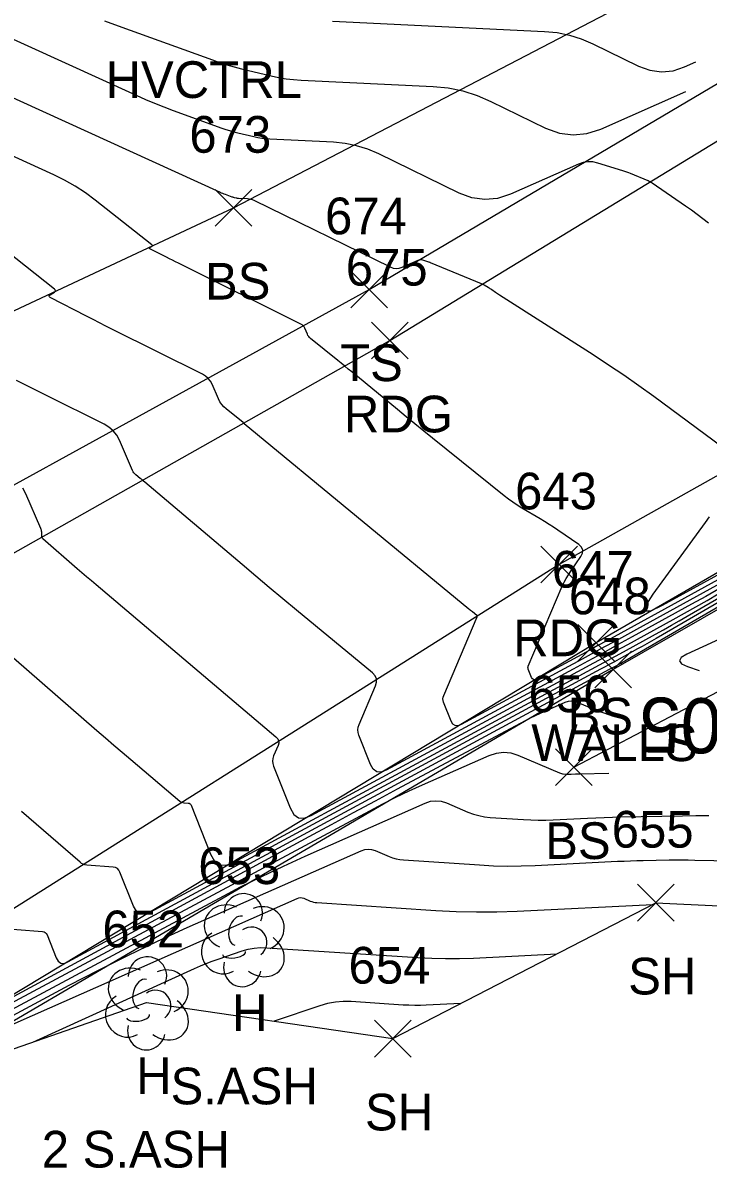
# Model space of a CAD drawing. Extents: x 1650836 to 1652450, y 332578 to 333908.
# Drawn here: x 1652071.1 to 1652108.4, y 332626 to 332688.4 of the extents above; entities that cross this region are included whole.
import ezdxf

# ---------------------------------------------------------------- set-up
doc = ezdxf.new("R2010")
doc.units = 0
for name, color, linetype in [('C_A', 7, 'Continuous'), ('L_A', 7, 'Continuous'), ('L_C', 7, 'Continuous'), ('L_I', 7, 'Continuous'), ('L_TIC', 7, 'Continuous'), ('LELB', 7, 'Continuous'), ('LSOGCMA', 7, 'Continuous'), ('LSOGCMA_T', 7, 'Continuous'), ('LSOGCMI', 7, 'Continuous'), ('LSOGP', 7, 'Continuous'), ('LTD', 7, 'Continuous'), ('LWS', 7, 'Continuous'), ('P_A', 7, 'Continuous'), ('P_I', 7, 'Continuous'), ('P_TIC', 7, 'Continuous'), ('PEU', 7, 'Continuous')]:
    doc.layers.add(name, color=color, linetype=linetype)

msp = doc.modelspace()

# ---------------------------------------------------------------- linework, layer by layer
at = {"layer": 'L_TIC'}
for points in [[(1652081.555, 332677.298), (1652083.555, 332679.298)], [(1652083.555, 332677.298), (1652081.555, 332679.298)], [(1652088.949, 332672.854), (1652090.949, 332674.854)], [(1652090.949, 332672.854), (1652088.949, 332674.854)], [(1652101.311, 332653.602), (1652103.311, 332655.602)], [(1652103.311, 332653.602), (1652101.311, 332655.602)], [(1652102.236, 332652.15), (1652104.236, 332654.15)], [(1652104.236, 332652.15), (1652102.236, 332654.15)], [(1652100.093, 332646.816), (1652102.093, 332648.816)], [(1652102.093, 332646.816), (1652100.093, 332648.816)], [(1652104.571, 332639.437), (1652106.571, 332641.437)], [(1652106.571, 332639.437), (1652104.571, 332641.437)], [(1652090.228, 332632.028), (1652092.228, 332634.028)], [(1652092.228, 332632.028), (1652090.228, 332634.028)]]:
    msp.add_lwpolyline(points, dxfattribs=at)
at = {"layer": 'LELB'}
for points in [[(1652048.756, 332662.461), (1652082.555, 332678.298), (1652130.366, 332703.201), (1652148.083, 332715.406), (1652159.47, 332726.367), (1652148.02, 332734.227), (1652128.413, 332739.339), (1652116.951, 332747.33), (1652106.793, 332756.875), (1652094.604, 332761.138), (1652083.802, 332764.466), (1652074.482, 332770.284), (1652065.17, 332770.428), (1652062.989, 332774.387), (1652054.537, 332784.724), (1652034.993, 332796.475), (1652025.062, 332801.1), (1652009.772, 332808.074), (1651988.967, 332816.401), (1651980.006, 332832.954), (1651960.575, 332843.477), (1651932.852, 332862.75), (1651890.753, 332886.019), (1651847.527, 332911.35)], [(1652054.928, 332654.589), (1652089.949, 332673.854), (1652132.975, 332699.313), (1652151.656, 332710.875), (1652169.833, 332727.743)], [(1652101.093, 332647.816), (1652114.189, 332654.693), (1652146.823, 332664.15), (1652153.664, 332667.075), (1652184.838, 332674.254)], [(1652114.452, 332661.6), (1652102.311, 332654.602), (1652064.084, 332631.537)]]:
    msp.add_lwpolyline(points, dxfattribs=at)
at = {"layer": 'LSOGCMA'}
for points in [[(1652075.521, 332688.493), (1652076.47, 332688.139), (1652081.4, 332686.353), (1652081.792, 332686.217), (1652082.188, 332686.092), (1652082.587, 332685.979), (1652082.989, 332685.876), (1652084.605, 332685.49), (1652085.011, 332685.402), (1652085.419, 332685.334), (1652085.83, 332685.286), (1652086.243, 332685.256), (1652093.433, 332684.907), (1652094.251, 332684.826), (1652095.048, 332684.665), (1652095.824, 332684.422), (1652096.58, 332684.099), (1652099.561, 332682.643), (1652100.308, 332682.367), (1652101.058, 332682.265), (1652101.812, 332682.338), (1652102.568, 332682.586), (1652107.206, 332684.634)], [(1652103.058, 332650.647), (1652102.687, 332650.778), (1652102.51, 332650.841), (1652102.335, 332650.908), (1652102.161, 332650.977), (1652101.988, 332651.048), (1652101.298, 332651.341), (1652101.125, 332651.396), (1652100.953, 332651.413), (1652100.781, 332651.393), (1652100.61, 332651.336), (1652099.268, 332650.743), (1652098.988, 332650.616), (1652098.711, 332650.484), (1652098.437, 332650.347), (1652098.165, 332650.204), (1652091.477, 332646.62), (1652090.272, 332645.974), (1652089.068, 332645.327), (1652087.865, 332644.678), (1652086.662, 332644.029), (1652069.011, 332634.495)]]:
    msp.add_lwpolyline(points, dxfattribs=at)
at = {"layer": 'LSOGCMI'}
for points in [[(1652108.436, 332677.463), (1652108.129, 332677.701), (1652107.819, 332677.935), (1652107.504, 332678.163), (1652107.186, 332678.387), (1652105.369, 332679.642), (1652105.317, 332679.676), (1652105.264, 332679.707), (1652105.209, 332679.735), (1652105.152, 332679.76), (1652104.192, 332680.158), (1652104.088, 332680.199), (1652103.984, 332680.238), (1652103.879, 332680.275), (1652103.773, 332680.309), (1652102.396, 332680.739), (1652102.132, 332680.798), (1652101.871, 332680.808), (1652101.613, 332680.769), (1652101.358, 332680.681), (1652097.642, 332679.039), (1652096.939, 332678.809), (1652096.24, 332678.742), (1652095.544, 332678.836), (1652094.851, 332679.093), (1652090.462, 332681.236), (1652089.869, 332681.49), (1652089.26, 332681.68), (1652088.634, 332681.807), (1652087.992, 332681.87), (1652084.538, 332682.038), (1652084.315, 332682.054), (1652084.094, 332682.08), (1652083.875, 332682.117), (1652083.657, 332682.163), (1652082.788, 332682.371), (1652082.572, 332682.426), (1652082.358, 332682.487), (1652082.145, 332682.554), (1652081.934, 332682.627), (1652079.284, 332683.587), (1652078.775, 332683.778), (1652078.269, 332683.978), (1652077.768, 332684.189), (1652077.271, 332684.41), (1652061.577, 332691.567)], [(1652058.73, 332689.68), (1652081.818, 332679.151), (1652081.887, 332679.12), (1652081.957, 332679.091), (1652082.028, 332679.063), (1652082.099, 332679.036), (1652082.469, 332678.902), (1652082.498, 332678.892), (1652082.528, 332678.882), (1652082.558, 332678.874), (1652082.588, 332678.866), (1652082.709, 332678.837), (1652082.74, 332678.831), (1652082.77, 332678.826), (1652082.801, 332678.822), (1652082.832, 332678.82), (1652083.314, 332678.796), (1652083.404, 332678.788), (1652083.491, 332678.77), (1652083.576, 332678.743), (1652083.659, 332678.708), (1652091.094, 332675.077), (1652091.255, 332675.017), (1652091.418, 332674.995), (1652091.581, 332675.011), (1652091.745, 332675.065), (1652092.613, 332675.448), (1652092.673, 332675.468), (1652092.733, 332675.478), (1652092.794, 332675.475), (1652092.855, 332675.462), (1652093.177, 332675.361), (1652093.202, 332675.353), (1652093.226, 332675.345), (1652093.251, 332675.336), (1652093.275, 332675.326), (1652096.052, 332674.176), (1652096.092, 332674.159), (1652096.132, 332674.14), (1652096.17, 332674.12), (1652096.208, 332674.098), (1652096.429, 332673.968), (1652096.479, 332673.939), (1652096.527, 332673.908), (1652096.575, 332673.877), (1652096.623, 332673.845), (1652096.836, 332673.698), (1652096.888, 332673.663), (1652096.94, 332673.629), (1652096.992, 332673.595), (1652097.044, 332673.561), (1652102.154, 332670.297), (1652102.993, 332669.751), (1652103.822, 332669.192), (1652104.642, 332668.619), (1652105.452, 332668.032), (1652109.658, 332664.932)], [(1652087.949, 332688.474), (1652099.502, 332687.913), (1652100.186, 332687.846), (1652100.852, 332687.711), (1652101.501, 332687.508), (1652102.132, 332687.238), (1652104.623, 332686.021), (1652105.247, 332685.79), (1652105.874, 332685.705), (1652106.504, 332685.766), (1652107.136, 332685.973), (1652107.753, 332686.246)], [(1652110.967, 332659.136), (1652103.297, 332654.925), (1652102.855, 332654.683), (1652102.413, 332654.442), (1652101.97, 332654.201), (1652101.527, 332653.961), (1652099.037, 332652.617), (1652098.959, 332652.588), (1652098.892, 332652.593), (1652098.838, 332652.631), (1652098.796, 332652.704), (1652098.615, 332653.16), (1652098.603, 332653.202), (1652098.599, 332653.243), (1652098.604, 332653.285), (1652098.617, 332653.326), (1652100.468, 332657.677), (1652100.568, 332657.894), (1652100.678, 332658.105), (1652100.799, 332658.309), (1652100.931, 332658.508), (1652101.482, 332659.29), (1652101.578, 332659.478), (1652101.59, 332659.651), (1652101.518, 332659.809), (1652101.363, 332659.952), (1652100.232, 332660.728), (1652099.991, 332660.89), (1652099.748, 332661.047), (1652099.503, 332661.201), (1652099.254, 332661.35), (1652098.255, 332661.939), (1652098.008, 332662.091), (1652097.767, 332662.251), (1652097.532, 332662.42), (1652097.303, 332662.598), (1652093.399, 332665.744), (1652092.917, 332666.133), (1652092.437, 332666.524), (1652091.958, 332666.915), (1652091.48, 332667.309), (1652088.997, 332669.359), (1652088.807, 332669.515), (1652088.616, 332669.671), (1652088.425, 332669.827), (1652088.234, 332669.982), (1652086.749, 332671.182), (1652086.696, 332671.23), (1652086.65, 332671.283), (1652086.611, 332671.341), (1652086.579, 332671.404), (1652086.437, 332671.732), (1652086.398, 332671.804), (1652086.349, 332671.865), (1652086.29, 332671.917), (1652086.221, 332671.96), (1652079.546, 332675.278), (1652079.385, 332675.359), (1652079.224, 332675.44), (1652079.064, 332675.521), (1652078.904, 332675.603), (1652078, 332676.07), (1652077.979, 332676.084), (1652077.971, 332676.1), (1652077.977, 332676.116), (1652077.997, 332676.133), (1652078.103, 332676.202), (1652078.124, 332676.22), (1652078.131, 332676.238), (1652078.125, 332676.257), (1652078.107, 332676.276), (1652075.014, 332678.719), (1652074.48, 332679.115), (1652073.925, 332679.478), (1652073.349, 332679.806), (1652072.753, 332680.1), (1652055.884, 332687.793)], [(1652109.24, 332657.915), (1652104.512, 332655.319), (1652103.527, 332654.78), (1652102.541, 332654.242), (1652101.554, 332653.705), (1652100.566, 332653.17), (1652094.951, 332650.138), (1652094.774, 332650.072), (1652094.624, 332650.084), (1652094.503, 332650.171), (1652094.409, 332650.335), (1652094.002, 332651.36), (1652093.975, 332651.453), (1652093.966, 332651.546), (1652093.977, 332651.639), (1652094.007, 332651.732), (1652095.827, 332656.01), (1652095.833, 332656.031), (1652095.831, 332656.051), (1652095.823, 332656.069), (1652095.808, 332656.086), (1652095.566, 332656.28), (1652095.52, 332656.318), (1652095.474, 332656.355), (1652095.427, 332656.393), (1652095.381, 332656.431), (1652083.14, 332666.535), (1652083.123, 332666.55), (1652083.106, 332666.564), (1652083.088, 332666.578), (1652083.071, 332666.592), (1652082.146, 332667.339), (1652082.018, 332667.456), (1652081.907, 332667.585), (1652081.812, 332667.727), (1652081.733, 332667.882), (1652081.386, 332668.68), (1652081.292, 332668.855), (1652081.173, 332669.006), (1652081.028, 332669.133), (1652080.859, 332669.235), (1652075.954, 332671.674), (1652075.6, 332671.85), (1652075.248, 332672.028), (1652074.896, 332672.207), (1652074.545, 332672.388), (1652072.563, 332673.41), (1652072.517, 332673.442), (1652072.5, 332673.477), (1652072.513, 332673.512), (1652072.556, 332673.549), (1652072.79, 332673.701), (1652072.834, 332673.74), (1652072.85, 332673.779), (1652072.838, 332673.821), (1652072.797, 332673.863), (1652066.014, 332679.221)], [(1652109.08, 332657.566), (1652108.298, 332657.128), (1652107.514, 332656.694), (1652104.275, 332654.916), (1652103.473, 332654.477), (1652102.67, 332654.039), (1652101.867, 332653.602), (1652101.062, 332653.167), (1652090.865, 332647.659), (1652090.589, 332647.557), (1652090.357, 332647.575), (1652090.167, 332647.711), (1652090.021, 332647.966), (1652089.389, 332649.56), (1652089.347, 332649.705), (1652089.333, 332649.85), (1652089.35, 332649.994), (1652089.397, 332650.138), (1652090.295, 332652.251), (1652090.351, 332652.451), (1652090.341, 332652.635), (1652090.265, 332652.803), (1652090.124, 332652.955), (1652085.993, 332656.368), (1652085.248, 332656.986), (1652084.504, 332657.606), (1652083.763, 332658.229), (1652083.023, 332658.854), (1652077.713, 332663.355), (1652077.654, 332663.405), (1652077.594, 332663.455), (1652077.534, 332663.504), (1652077.473, 332663.553), (1652077.231, 332663.749), (1652077.174, 332663.801), (1652077.125, 332663.858), (1652077.083, 332663.921), (1652077.048, 332663.99), (1652076.335, 332665.629), (1652076.186, 332665.907), (1652075.996, 332666.146), (1652075.767, 332666.348), (1652075.497, 332666.511), (1652072.361, 332668.07), (1652071.816, 332668.342), (1652071.272, 332668.617), (1652070.728, 332668.893)], [(1652071.052, 332663.039), (1652071.218, 332662.73), (1652072.042, 332660.836), (1652072.059, 332660.79), (1652072.071, 332660.743), (1652072.079, 332660.694), (1652072.082, 332660.645), (1652072.083, 332660.447), (1652072.088, 332660.399), (1652072.102, 332660.356), (1652072.125, 332660.317), (1652072.158, 332660.282), (1652074.034, 332658.652), (1652074.29, 332658.43), (1652074.547, 332658.208), (1652074.805, 332657.988), (1652075.064, 332657.769), (1652084.865, 332649.478), (1652084.96, 332649.373), (1652085.01, 332649.259), (1652085.017, 332649.134), (1652084.979, 332648.998), (1652084.74, 332648.436), (1652084.694, 332648.295), (1652084.678, 332648.153), (1652084.691, 332648.012), (1652084.733, 332647.87), (1652085.634, 332645.596), (1652085.832, 332645.25), (1652086.089, 332645.066), (1652086.404, 332645.042), (1652086.779, 332645.18), (1652101.558, 332653.163), (1652102.179, 332653.499), (1652102.799, 332653.836), (1652103.419, 332654.174), (1652104.038, 332654.513), (1652106.513, 332655.872), (1652107.13, 332656.213), (1652107.746, 332656.558), (1652108.359, 332656.907), (1652108.971, 332657.26)], [(1652066.86, 332656.989), (1652075.112, 332649.816), (1652075.57, 332649.419), (1652076.029, 332649.024), (1652076.489, 332648.631), (1652076.951, 332648.239), (1652079.633, 332645.97), (1652079.681, 332645.936), (1652079.732, 332645.91), (1652079.787, 332645.892), (1652079.845, 332645.883), (1652080.085, 332645.865), (1652080.14, 332645.853), (1652080.186, 332645.83), (1652080.222, 332645.793), (1652080.249, 332645.743), (1652081.306, 332643.076), (1652081.521, 332642.701), (1652081.8, 332642.5), (1652082.143, 332642.474), (1652082.55, 332642.624), (1652102.055, 332653.159), (1652102.492, 332653.396), (1652102.929, 332653.633), (1652103.365, 332653.871), (1652103.801, 332654.11), (1652105.544, 332655.067), (1652105.979, 332655.307), (1652106.412, 332655.55), (1652106.844, 332655.796), (1652107.274, 332656.044), (1652115.608, 332660.886)], [(1652108.479, 332661.466), (1652108.253, 332661.149), (1652105.399, 332657.253), (1652105.018, 332656.65), (1652104.98, 332656.347), (1652105.285, 332656.346), (1652105.933, 332656.645), (1652112.693, 332660.356)], [(1652069.326, 332639.091), (1652072.141, 332638.871), (1652072.226, 332638.854), (1652072.296, 332638.817), (1652072.352, 332638.761), (1652072.393, 332638.685), (1652072.888, 332637.436), (1652072.998, 332637.244), (1652073.141, 332637.142), (1652073.316, 332637.128), (1652073.524, 332637.205), (1652103.047, 332653.152), (1652103.117, 332653.189), (1652103.187, 332653.227), (1652103.257, 332653.265), (1652103.326, 332653.304), (1652103.605, 332653.457), (1652103.675, 332653.495), (1652103.744, 332653.534), (1652103.813, 332653.573), (1652103.882, 332653.613), (1652116.085, 332660.703)], [(1652115.847, 332660.794), (1652105.578, 332654.829), (1652105.329, 332654.685), (1652105.078, 332654.542), (1652104.827, 332654.401), (1652104.574, 332654.262), (1652103.564, 332653.707), (1652103.311, 332653.568), (1652103.058, 332653.43), (1652102.804, 332653.293), (1652102.551, 332653.155), (1652078.037, 332639.914), (1652077.73, 332639.801), (1652077.471, 332639.821), (1652077.26, 332639.972), (1652077.097, 332640.256), (1652076.365, 332642.102), (1652076.304, 332642.214), (1652076.222, 332642.298), (1652076.118, 332642.352), (1652075.992, 332642.377), (1652074.557, 332642.489), (1652074.458, 332642.504), (1652074.364, 332642.535), (1652074.277, 332642.58), (1652074.196, 332642.64), (1652070.997, 332645.407)], [(1652113.629, 332656.905), (1652107.258, 332653.977), (1652106.953, 332653.794), (1652106.857, 332653.621), (1652106.969, 332653.457), (1652107.289, 332653.303), (1652107.925, 332653.08)], [(1652066.615, 332632.927), (1652089.976, 332645.447), (1652090.687, 332645.819), (1652091.404, 332646.178), (1652092.128, 332646.523), (1652092.859, 332646.855), (1652096.482, 332648.457), (1652096.874, 332648.587), (1652097.267, 332648.633), (1652097.66, 332648.593), (1652098.053, 332648.469), (1652100.321, 332647.507), (1652100.37, 332647.488), (1652100.42, 332647.474), (1652100.472, 332647.464), (1652100.524, 332647.458), (1652100.735, 332647.444), (1652100.788, 332647.442), (1652100.841, 332647.441), (1652100.894, 332647.441), (1652100.947, 332647.443), (1652101.192, 332647.455), (1652101.25, 332647.458), (1652101.309, 332647.46), (1652101.367, 332647.462), (1652101.426, 332647.463), (1652103.012, 332647.492)], [(1652064.109, 332631.216), (1652081.786, 332640.69), (1652082.936, 332641.292), (1652084.097, 332641.872), (1652085.269, 332642.431), (1652086.451, 332642.967), (1652092.998, 332645.862), (1652093.288, 332645.959), (1652093.579, 332645.992), (1652093.87, 332645.963), (1652094.162, 332645.871), (1652095.329, 332645.375), (1652095.624, 332645.264), (1652095.925, 332645.179), (1652096.233, 332645.12), (1652096.546, 332645.086), (1652098.347, 332644.968), (1652098.752, 332644.947), (1652099.158, 332644.938), (1652099.564, 332644.94), (1652099.97, 332644.955), (1652101.849, 332645.048), (1652102.297, 332645.069), (1652102.746, 332645.086), (1652103.195, 332645.099), (1652103.644, 332645.11), (1652107.024, 332645.172), (1652107.737, 332645.182), (1652108.45, 332645.184)], [(1652064.137, 332630.863), (1652073.605, 332635.937), (1652075.19, 332636.767), (1652076.79, 332637.567), (1652078.405, 332638.337), (1652080.035, 332639.076), (1652089.513, 332643.267), (1652089.702, 332643.33), (1652089.891, 332643.352), (1652090.08, 332643.333), (1652090.27, 332643.273), (1652091.029, 332642.951), (1652091.221, 332642.878), (1652091.416, 332642.823), (1652091.616, 332642.784), (1652091.82, 332642.763), (1652095.958, 332642.491), (1652096.716, 332642.452), (1652097.475, 332642.435), (1652098.234, 332642.44), (1652098.992, 332642.467), (1652103.483, 332642.69), (1652103.833, 332642.706), (1652104.183, 332642.72), (1652104.533, 332642.73), (1652104.884, 332642.738), (1652106.285, 332642.764), (1652106.635, 332642.769), (1652106.986, 332642.77), (1652107.336, 332642.768), (1652107.686, 332642.762), (1652111.857, 332642.676)], [(1652064.165, 332630.509), (1652068.125, 332632.632), (1652068.788, 332632.979), (1652069.458, 332633.314), (1652070.133, 332633.635), (1652070.815, 332633.945), (1652086.029, 332640.672), (1652086.116, 332640.701), (1652086.203, 332640.711), (1652086.291, 332640.702), (1652086.378, 332640.675), (1652086.728, 332640.526), (1652086.817, 332640.493), (1652086.907, 332640.467), (1652086.999, 332640.449), (1652087.093, 332640.439), (1652093.569, 332640.014), (1652094.68, 332639.957), (1652095.792, 332639.932), (1652096.903, 332639.939), (1652098.015, 332639.978), (1652105.395, 332640.346)], [(1652071.616, 332632.844), (1652080.433, 332636.857), (1652080.749, 332636.996), (1652081.068, 332637.126), (1652081.39, 332637.249), (1652081.715, 332637.364), (1652083.022, 332637.808), (1652083.351, 332637.902), (1652083.685, 332637.963), (1652084.022, 332637.991), (1652084.365, 332637.985), (1652092.594, 332637.444), (1652093.351, 332637.405), (1652094.108, 332637.388), (1652094.866, 332637.393), (1652095.623, 332637.42), (1652100.169, 332637.646)], [(1652094.942, 332634.946), (1652093.054, 332634.852), (1652092.739, 332634.841), (1652092.425, 332634.839), (1652092.11, 332634.846), (1652091.796, 332634.862), (1652088.965, 332635.048), (1652088.531, 332635.056), (1652088.102, 332635.021), (1652087.679, 332634.944), (1652087.261, 332634.824), (1652084.772, 332633.979)]]:
    msp.add_lwpolyline(points, dxfattribs=at)
at = {"layer": 'LSOGP'}
msp.add_lwpolyline([(1651984.523, 332752.343), (1651991.57, 332730.62), (1651991.353, 332729.831), (1651992.861, 332722.96), (1651995.915, 332712.612), (1651995.92, 332711.781), (1652013.872, 332713.448), (1652022.272, 332696.192), (1652039.797, 332682.479), (1652040.117, 332681.915), (1652040.875, 332679.562), (1652040.399, 332672.943), (1652048.756, 332662.461), (1652054.928, 332654.589), (1652056.971, 332651.823), (1652062.738, 332635.184), (1652064.084, 332631.537), (1652064.185, 332630.255), (1652077.816, 332635.004), (1652091.228, 332633.028), (1652105.571, 332640.437), (1652132.417, 332639.149), (1652165.837, 332638.134)], dxfattribs=at)
at = {"layer": 'LTD'}
for p, q in [((1652083.044, 332638.449), (1652083.044, 332638.449)), ((1652083.044, 332638.449), (1652083.044, 332638.449)), ((1652077.816, 332635.004), (1652077.816, 332635.004)), ((1652077.816, 332635.004), (1652077.816, 332635.004))]:
    msp.add_line(p, q, dxfattribs=at)
for centre in [(1652083.09, 332639.883), (1652077.863, 332636.438)]:
    msp.add_arc(centre, 1.047, 335.52715, 180.95627, dxfattribs=at)
for centre, major_axis, ratio, start_param, end_param in [((1652082.252, 332639.115), (1.21, -0.512), 0.895232, 1.570796, 4.712389), ((1652084.085, 332639.032), (-1.141, -0.483), 0.949671, 1.570796, 4.712389), ((1652082.835, 332638.907), (-0.208, -0.792), 0.645439, 3.141593, 6.283185), ((1652083.544, 332638.282), (-0.5, 0.667), 0.989748, 3.141593, 6.283185), ((1652081.96, 332637.74), (0.584, -1.042), 0.959034, 3.141593, 6.283185), ((1652084.044, 332637.615), (-1.09, 0.792), 0.841452, 1.570796, 4.712389), ((1652082.585, 332637.699), (-0.625, -0.083), 0.423636, 0, 3.141593), ((1652083.044, 332636.949), (0.265, 1.061), 0.942809, 1.570796, 4.712389), ((1652077.024, 332635.671), (1.21, -0.512), 0.895232, 1.570796, 4.712389), ((1652078.858, 332635.588), (-1.141, -0.483), 0.949671, 1.570796, 4.712389), ((1652077.608, 332635.462), (-0.208, -0.792), 0.645439, 3.141593, 6.283185), ((1652076.733, 332634.295), (0.584, -1.042), 0.959034, 3.141593, 6.283185), ((1652078.316, 332634.837), (-0.5, 0.667), 0.989748, 3.141593, 6.283185), ((1652078.816, 332634.171), (-1.09, 0.792), 0.841452, 1.570796, 4.712389), ((1652077.358, 332634.254), (-0.625, -0.083), 0.423636, 0, 3.141593), ((1652077.816, 332633.504), (0.265, 1.061), 0.942809, 1.570796, 4.712389)]:
    msp.add_ellipse(centre, major_axis=major_axis, ratio=ratio, start_param=start_param, end_param=end_param, dxfattribs=at)
at = {"layer": 'LWS'}
msp.add_lwpolyline([(1652208.992, 332628.311), (1652198.531, 332678.869), (1652152.626, 332670.878), (1652142.717, 332668.181), (1652116.306, 332660.618), (1652103.236, 332653.15), (1652064.185, 332630.255)], dxfattribs=at)
at = {"layer": 'P_TIC'}
for points in [[(1652090.078, 332670.061), (1652092.078, 332672.061)], [(1652092.078, 332670.061), (1652090.078, 332672.061)], [(1652099.303, 332657.865), (1652101.303, 332659.865)], [(1652101.303, 332657.865), (1652099.303, 332659.865)]]:
    msp.add_lwpolyline(points, dxfattribs=at)
at = {"layer": 'PEU'}
for points in [[(1652056.971, 332651.823), (1652091.078, 332671.061), (1652133.854, 332697.145), (1652158.219, 332712.634)], [(1652178.884, 332701.373), (1652143.147, 332682.921), (1652100.303, 332658.865), (1652062.738, 332635.184)]]:
    msp.add_lwpolyline(points, dxfattribs=at)

# ---------------------------------------------------------------- texts
at = {"layer": 'C_A'}
msp.add_text('HVCTRL', height=2, dxfattribs=at).set_placement((1652075.581, 332684.281))
at = {"layer": 'L_A'}
for s, p in [('BS', (1652080.996, 332673.298)), ('TS', (1652088.359, 332668.854)), ('BS', (1652100.752, 332649.602)), ('WALLS', (1652098.78, 332648.15)), ('BS', (1652099.534, 332642.816)), ('SH', (1652104.06, 332635.437)), ('H', (1652082.477, 332633.449)), ('H', (1652077.249, 332630.004)), ('SH', (1652089.717, 332628.028))]:
    msp.add_text(s, height=2, dxfattribs=at).set_placement(p)
at = {"layer": 'L_C'}
for s, p in [('S.ASH', (1652079.122, 332629.449)), ('2 S.ASH', (1652072.1, 332626.004))]:
    msp.add_text(s, height=2, dxfattribs=at).set_placement(p)
at = {"layer": 'L_I'}
for s, p in [('673', (1652080.146, 332681.298)), ('674', (1652087.54, 332676.854)), ('647', (1652099.901, 332657.602)), ('648', (1652100.827, 332656.15)), ('656', (1652098.629, 332650.816)), ('655', (1652103.162, 332643.437)), ('653', (1652080.634, 332641.449)), ('652', (1652075.407, 332638.004)), ('654', (1652088.819, 332636.028))]:
    msp.add_text(s, height=2, dxfattribs=at).set_placement(p)
at = {"layer": 'LSOGCMA_T'}
msp.add_text('805', height=3, rotation=179.15833, dxfattribs=at).set_placement((1652111.399, 332651.528))
at = {"layer": 'P_A'}
for p in [(1652088.566, 332666.061), (1652097.792, 332653.865)]:
    msp.add_text('RDG', height=2, dxfattribs=at).set_placement(p)
at = {"layer": 'P_I'}
for s, p in [('675', (1652088.669, 332674.061)), ('643', (1652097.894, 332661.865))]:
    msp.add_text(s, height=2, dxfattribs=at).set_placement(p)

doc.saveas('drawing.dxf')
